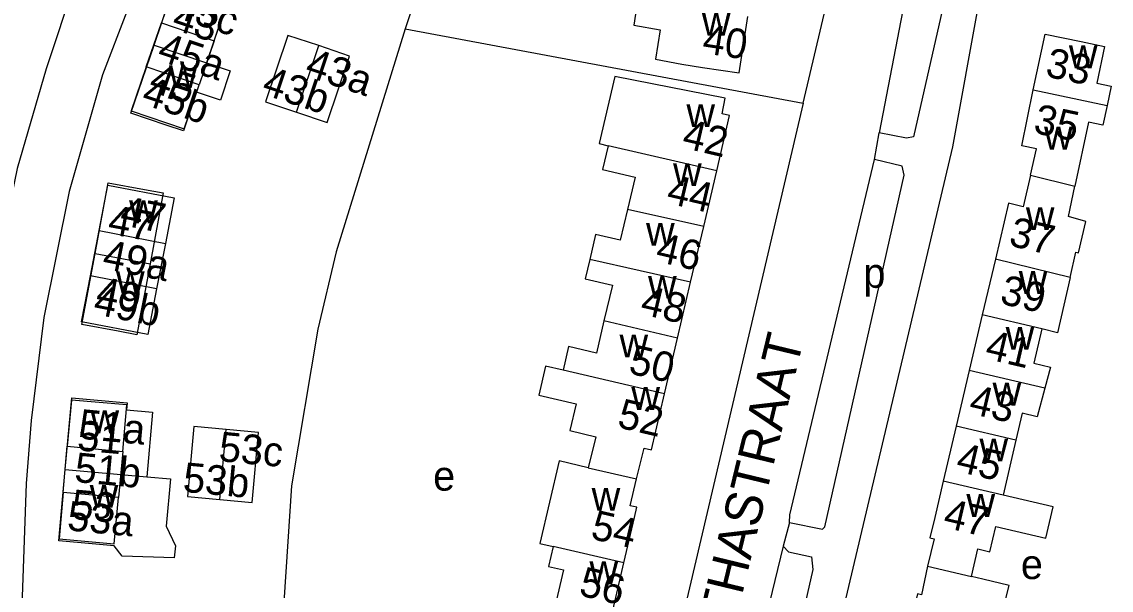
# Model space of a CAD drawing. Extents: x 163012 to 165277, y 382513 to 383987.
# Drawn here: x 163733.4 to 163880.5, y 383490.2 to 383566.9 of the extents above; entities that cross this region are included whole.
import ezdxf

# ---------------------------------------------------------------- set-up
doc = ezdxf.new("R2010")
doc.units = 0
for name, color, linetype in [('BLT_Basislijn', 7, 'Continuous'), ('BLT_Bebouwing', 7, 'Continuous'), ('BLT_Centroide', 7, 'Continuous'), ('BLT_Huisnummer', 7, 'Continuous'), ('BLT_Huisnummer_ tussenligend', 7, 'Continuous'), ('BLT_Huisnummer_zonder_bebouwing', 7, 'Continuous'), ('BLT_Onderverdeling_panden', 7, 'Continuous'), ('BLT_Plantopo', 7, 'Continuous'), ('BLT_Straatnaam', 7, 'Continuous')]:
    doc.layers.add(name, color=color, linetype=linetype)

msp = doc.modelspace()

# ---------------------------------------------------------------- linework, layer by layer
at = {"layer": 'BLT_Basislijn'}
for p, q in [((163800.17, 383612.48), (163785.18, 383565.97)), ((163785.18, 383565.97), (163838.88, 383555.93)), ((163838.88, 383555.93), (163817.82, 383466.23)), ((163848.51, 383548.34), (163849.14, 383551.93)), ((163837.05, 383499.34), (163836.16, 383496.12)), ((163836.16, 383496.12), (163822.39, 383439.12))]:
    msp.add_line(p, q, dxfattribs=at)
for points in [[(163770.03, 383754.82), (163772.51, 383738.33), (163775.97, 383708.9), (163776.53, 383701.83), (163776.56, 383693.4), (163775.74, 383675), (163774.24, 383662.15), (163771.68, 383646.14), (163766.37, 383625.25), (163749.08, 383573.42), (163747.62, 383568.32), (163744.3, 383559.76), (163739.81, 383544.03), (163736.41, 383526.99), (163734.71, 383513.11), (163734.03, 383504.57), (163733.07, 383477.8), (163734.15, 383457.39), (163735.99, 383441.47), (163739.37, 383421.06)], [(163858.48, 383609.78), (163862.64, 383609.43), (163862.86, 383608.82), (163859.49, 383576.6), (163853.78, 383551.38), (163852.82, 383551.19), (163849.14, 383551.93)], [(163858.48, 383609.78), (163855.5, 383584.89), (163849.14, 383551.93)], [(163838.88, 383555.93), (163842.12, 383569.65), (163846.07, 383595.44), (163847.11, 383607.78)], [(163748.24, 383595.3), (163736.71, 383560.56), (163732.8, 383547.12), (163729.29, 383530.23), (163728.07, 383520.74), (163726.17, 383499.48), (163726.13, 383462.51), (163728.06, 383443.75)], [(163862.59, 383569.6), (163859.01, 383550.05), (163841.02, 383473.95)], [(163785.18, 383565.97), (163775.86, 383535.86), (163773.36, 383525.41), (163769.81, 383504.26), (163768.57, 383485.13), (163768.89, 383475.66)], [(163837.05, 383499.34), (163837.07, 383500.37), (163848.51, 383548.34)], [(163837.05, 383499.34), (163841.48, 383498.42), (163841.8, 383498.74), (163852.52, 383546.2), (163852.26, 383547.41), (163848.51, 383548.34)], [(163836.16, 383496.12), (163836.91, 383495.37), (163839.98, 383494.69), (163840.17, 383492.97), (163827.82, 383438.41), (163826.54, 383438.14), (163822.39, 383439.12)]]:
    msp.add_lwpolyline(points, dxfattribs=at)
at = {"layer": 'BLT_Bebouwing'}
for p, q in [((163825.45, 383539.28), (163827.21, 383546.82)), ((163823.69, 383531.75), (163825.45, 383539.28)), ((163864.82, 383534.88), (163863.05, 383527.36)), ((163821.93, 383524.22), (163823.69, 383531.75)), ((163863.05, 383527.36), (163861.29, 383519.84)), ((163820.16, 383516.68), (163821.93, 383524.22)), ((163861.29, 383519.84), (163859.53, 383512.31)), ((163859.53, 383512.31), (163857.78, 383504.9)), ((163867.59, 383510.43), (163865.86, 383503)), ((163812.94, 383486.37), (163814.69, 383493.88))]:
    msp.add_line(p, q, dxfattribs=at)
for points in [[(163751.27, 383563.78), (163754.38, 383572.99), (163759.12, 383571.39), (163761.46, 383570.59), (163758.36, 383561.39)], [(163817.43, 383569.9), (163816.58, 383570.05), (163816.03, 383566.48), (163819.57, 383565.85), (163818.95, 383561.87), (163822.5, 383561.2), (163825.28, 383560.77), (163830.22, 383560.02), (163831.4, 383567.65)], [(163869.94, 383557.72), (163871.52, 383565.26), (163876.41, 383564.24), (163879.53, 383563.59), (163878.5, 383558.62), (163880.45, 383558.21), (163879.89, 383555.64)], [(163758.36, 383561.39), (163761.55, 383560.31), (163760.22, 383556.36), (163757.02, 383557.43), (163755.25, 383552.19), (163752.9, 383552.98), (163748.16, 383554.58), (163751.27, 383563.78)], [(163827.93, 383554.51), (163828.34, 383556.6), (163813.45, 383559.53), (163811.33, 383550.48), (163812.56, 383550.18)], [(163869.55, 383546.2), (163870.37, 383549.76), (163868.37, 383550.18), (163869.94, 383557.72)], [(163827.21, 383546.82), (163828.95, 383554.28), (163827.93, 383554.51)], [(163879.89, 383555.64), (163879.31, 383552.98), (163877.4, 383553.38), (163875.56, 383544.73)], [(163812.56, 383550.18), (163811.8, 383546.99), (163816.2, 383545.93), (163815.18, 383541.6)], [(163869.55, 383546.2), (163868.57, 383541.96), (163866.59, 383542.43), (163864.82, 383534.88)], [(163743.31, 383535.63), (163745.08, 383545.2), (163750, 383544.29), (163752.51, 383543.82), (163750.73, 383534.25)], [(163874.91, 383532.42), (163875.67, 383535.8), (163876.05, 383535.72), (163877.04, 383539.98), (163874.67, 383540.65), (163875.56, 383544.73)], [(163815.18, 383541.6), (163814.19, 383537.42), (163810.87, 383538.22), (163810.07, 383534.85)], [(163750.73, 383534.25), (163748.96, 383524.68), (163746.45, 383525.15), (163741.54, 383526.06), (163743.31, 383535.63)], [(163810.07, 383534.85), (163809.45, 383532.24), (163813.13, 383531.35), (163811.99, 383526.55)], [(163874.91, 383532.42), (163873.19, 383524.93), (163871.11, 383525.48)], [(163811.99, 383526.55), (163810.97, 383522.2), (163807.22, 383523.1), (163806.47, 383519.89)], [(163871.11, 383525.48), (163870.03, 383520.83), (163872.27, 383520.3), (163871.5, 383517.45)], [(163806.47, 383519.89), (163804.12, 383520.44), (163803.2, 383516.51), (163808.24, 383515.34), (163807.39, 383511.73), (163810.88, 383510.91), (163809.88, 383506.72)], [(163739.29, 383506.5), (163740.16, 383516.17), (163747.63, 383515.5), (163747.54, 383514.55), (163751.06, 383514.24), (163750.29, 383505.51)], [(163816.37, 383505.2), (163817.44, 383509.38), (163818.4, 383509.15), (163820.16, 383516.68)], [(163871.5, 383517.45), (163870.47, 383513.61), (163868.45, 383514.08), (163867.59, 383510.43)], [(163809.88, 383506.72), (163805.94, 383507.65), (163803.33, 383496.49), (163805.13, 383496.08)], [(163750.29, 383505.51), (163753.49, 383505.23), (163752.92, 383498.83), (163754.15, 383496.19), (163754.01, 383494.55), (163746.99, 383494.77), (163745.91, 383496.16), (163743.41, 383496.38), (163738.43, 383496.83), (163739.29, 383506.5)], [(163814.69, 383493.88), (163816.12, 383500), (163816.45, 383501.38), (163815.53, 383501.59), (163816.37, 383505.2)], [(163857.78, 383504.9), (163856.64, 383500), (163855.99, 383497.26), (163856.55, 383497.13), (163855.67, 383493.44)], [(163861.59, 383492.04), (163862.44, 383495.77), (163864.08, 383495.38), (163864.88, 383498.79), (163871.63, 383497.21), (163872.61, 383501.42), (163865.86, 383503)], [(163805.13, 383496.08), (163804.52, 383493.38), (163806.52, 383492.93), (163805.4, 383488.13)], [(163855.67, 383493.44), (163854.84, 383489.54), (163854.29, 383489.68), (163852.4, 383481.99)], [(163866.74, 383478.58), (163867.69, 383482.62), (163864.78, 383483.3), (163866.7, 383490.82), (163863.14, 383491.67), (163861.59, 383492.04)]]:
    msp.add_lwpolyline(points, dxfattribs=at)
at = {"layer": 'BLT_Onderverdeling_panden'}
for p, q in [((163751.27, 383563.78), (163758.36, 383561.39)), ((163869.94, 383557.72), (163879.89, 383555.64)), ((163827.21, 383546.82), (163812.56, 383550.18)), ((163869.55, 383546.2), (163875.56, 383544.73)), ((163825.45, 383539.28), (163815.18, 383541.6)), ((163743.31, 383535.63), (163750.73, 383534.25)), ((163823.69, 383531.75), (163810.07, 383534.85)), ((163874.91, 383532.42), (163864.82, 383534.88)), ((163821.93, 383524.22), (163811.99, 383526.55)), ((163871.11, 383525.48), (163863.05, 383527.36)), ((163820.16, 383516.68), (163806.47, 383519.89)), ((163871.5, 383517.45), (163861.29, 383519.84)), ((163867.59, 383510.43), (163859.53, 383512.31)), ((163739.29, 383506.5), (163750.29, 383505.51)), ((163809.88, 383506.72), (163816.37, 383505.2)), ((163865.86, 383503), (163857.78, 383504.9)), ((163814.69, 383493.88), (163805.13, 383496.08)), ((163855.67, 383493.44), (163861.59, 383492.04))]:
    msp.add_line(p, q, dxfattribs=at)
at = {"layer": 'BLT_Plantopo'}
for p, q in [((163750.23, 383560.86), (163752.26, 383566.78)), ((163752.26, 383566.78), (163759.38, 383564.34)), ((163759.38, 383564.34), (163757.35, 383558.42)), ((163770.48, 383554.71), (163773.5, 383563.7)), ((163757.35, 383558.42), (163750.23, 383560.86)), ((163742.68, 383532.61), (163743.87, 383538.74)), ((163743.87, 383538.74), (163752.8, 383537.01)), ((163752.8, 383537.01), (163751.61, 383530.89)), ((163751.61, 383530.89), (163742.68, 383532.61)), ((163760.16, 383502.42), (163761.01, 383511.88)), ((163739.01, 383503.38), (163739.57, 383509.61)), ((163739.57, 383509.61), (163747.04, 383508.93)), ((163747.04, 383508.93), (163746.48, 383502.7)), ((163746.48, 383502.7), (163739.01, 383503.38))]:
    msp.add_line(p, q, dxfattribs=at)
for points in [[(163759.38, 383564.34), (163761.41, 383570.27), (163754.29, 383572.7), (163752.26, 383566.78)], [(163773.5, 383563.7), (163769.35, 383565.09), (163766.33, 383556.11), (163770.48, 383554.71)], [(163770.48, 383554.71), (163774.64, 383553.32), (163777.66, 383562.3), (163773.5, 383563.7)], [(163750.23, 383560.86), (163748.19, 383554.9), (163755.32, 383552.46), (163757.35, 383558.42)], [(163743.87, 383538.74), (163745.05, 383544.87), (163753.98, 383543.15), (163752.8, 383537.01)], [(163751.61, 383530.89), (163750.42, 383524.7), (163741.49, 383526.43), (163742.68, 383532.61)], [(163747.04, 383508.93), (163747.61, 383515.19), (163740.14, 383515.86), (163739.57, 383509.61)], [(163761.01, 383511.88), (163756.66, 383512.27), (163755.8, 383502.82), (163760.16, 383502.42)], [(163760.16, 383502.42), (163764.51, 383502.03), (163765.36, 383511.49), (163761.01, 383511.88)], [(163739.01, 383503.38), (163738.45, 383497.13), (163745.91, 383496.46), (163746.48, 383502.7)]]:
    msp.add_lwpolyline(points, dxfattribs=at)

# ---------------------------------------------------------------- texts
at = {"layer": 'BLT_Centroide'}
for s, p in [('w', (163825.21, 383565.03)), ('w', (163874.74, 383560.66)), ('w', (163753.27, 383557.98)), ('w', (163823.12, 383552.72)), ('w', (163871.39, 383549.67)), ('w', (163821.32, 383544.75)), ('w', (163747.91, 383539.73)), ('w', (163868.93, 383538.82)), ('w', (163817.67, 383536.69)), ('p', (163847, 383531.01)), ('w', (163746.14, 383530.16)), ('w', (163817.94, 383529.53)), ('w', (163867.97, 383530.19)), ('w', (163866.2, 383522.66)), ('w', (163814.09, 383521.62)), ('w', (163815.69, 383514.53)), ('w', (163864.44, 383515.12)), ('w', (163742.69, 383511.38)), ('w', (163862.67, 383507.59)), ('e', (163788.94, 383503.63)), ('w', (163742.59, 383501.33)), ('w', (163810.33, 383500.91)), ('w', (163860.91, 383500.09)), ('w', (163810.04, 383491)), ('e', (163868.26, 383491.69))]:
    msp.add_text(s, height=4, dxfattribs=at).set_placement(p)
at = {"layer": 'BLT_Huisnummer'}
for s, rotation, p in [('43', 341.33, (163753.49, 383566.04)), ('40', 351.2725, (163825.14, 383562.72)), ('33', 348.2263, (163871.43, 383559.56)), ('45', 341.3259, (163750.38, 383557.64)), ('35', 348.2182, (163869.81, 383551.96)), ('42', 346.847, (163822.38, 383549.96)), ('47', 349.4969, (163744.88, 383538.34)), ('37', 346.8399, (163866.48, 383536.75)), ('46', 346.8381, (163818.81, 383534.63)), ('49', 349.5035, (163743.28, 383528.63)), ('41', 346.8406, (163863.27, 383521.48)), ('52', 346.8453, (163813.64, 383512.21)), ('51', 354.8976, (163740.8, 383509.08)), ('53', 354.8948, (163740.02, 383499.82)), ('47', 346.8113, (163857.62, 383498.72)), ('54', 346.8501, (163810.04, 383497.17))]:
    msp.add_text(s, height=4, rotation=rotation, dxfattribs=at).set_placement(p)
at = {"layer": 'BLT_Huisnummer_ tussenligend'}
for s, rotation, p in [('44', 346.847, (163820.28, 383542.48)), ('39', 346.8399, (163865.27, 383528.92)), ('48', 346.8381, (163816.74, 383527.5)), ('50', 346.8381, (163815.16, 383519.5)), ('43', 346.8406, (163861.09, 383514.1)), ('45', 346.8406, (163859.35, 383506.27)), ('56', 346.8501, (163808.47, 383489.52))]:
    msp.add_text(s, height=4, rotation=rotation, dxfattribs=at).set_placement(p)
at = {"layer": 'BLT_Huisnummer_zonder_bebouwing'}
for s, rotation, p in [('43c', 341.5724, (163753.66, 383567.66)), ('45a', 341.5724, (163751.53, 383561.78)), ('43a', 341.5724, (163771.45, 383559.66)), ('43b', 341.5724, (163765.65, 383557.23)), ('45b', 341.5724, (163749.41, 383555.89)), ('47', 348.5724, (163746.52, 383539.55)), ('49a', 348.5724, (163744.15, 383533.65)), ('49b', 348.5724, (163742.94, 383527.51)), ('51a', 354.5724, (163741.02, 383510.67)), ('53c', 354.5724, (163759.9, 383507.63)), ('51b', 354.5724, (163740.43, 383504.82)), ('53b', 354.5724, (163755.06, 383503.49)), ('53a', 354.5724, (163739.45, 383498.28))]:
    msp.add_text(s, height=4, rotation=rotation, dxfattribs=at).set_placement(p)
at = {"layer": 'BLT_Straatnaam'}
msp.add_text('GENERAAL BOTHASTRAAT', height=5, rotation=76.4257, dxfattribs=at).set_placement((163818.42, 383438.87))

doc.saveas('drawing.dxf')
